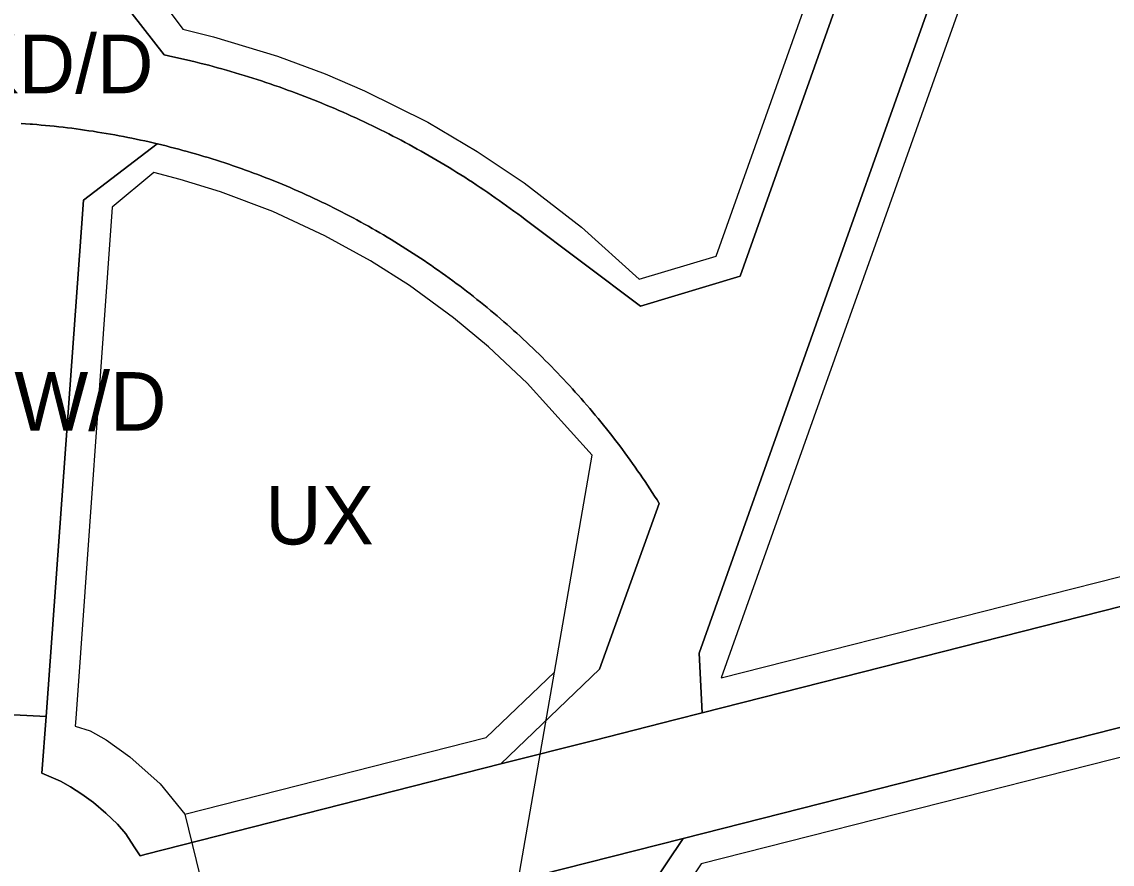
# Model space of a CAD drawing. Extents: x -297746 to -295403, y 27112 to 28877.
# Drawn here: x -297020 to -296833.6, y 27745.5 to 27889.5 of the extents above; entities that cross this region are included whole.
import ezdxf

# ---------------------------------------------------------------- set-up
doc = ezdxf.new("R2010")
doc.units = 0
for name, color, linetype in [('linie_rozgraniczajace', 7, 'Continuous'), ('linie_zabudowy_nieprzekraczalne', 7, 'Continuous'), ('linie_zabudowy_obowiazujace', 7, 'Continuous'), ('oznaczenia_przeznaczen', 7, 'Continuous')]:
    doc.layers.add(name, color=color, linetype=linetype)

msp = doc.modelspace()

# ---------------------------------------------------------------- linework, layer by layer
at = {"layer": 'linie_rozgraniczajace'}
for points in [[(-296820.49, 28048.576), (-296840.945, 27963.7), (-296846.998, 27942.631), (-296904.241, 27781.587), (-296903.708, 27771.365), (-296908.226, 27770.217), (-296922.224, 27766.659), (-296938.097, 27762.625)], [(-296746.59, 27811.296), (-296903.708, 27771.365), (-296904.241, 27781.587), (-296846.998, 27942.631), (-296840.945, 27963.7), (-296820.49, 28048.576)], [(-296943.628, 27862.473), (-296942.968, 27862.045), (-296942.311, 27861.614), (-296941.656, 27861.18), (-296941.003, 27860.742), (-296940.353, 27860.301), (-296939.704, 27859.857), (-296939.058, 27859.409), (-296938.415, 27858.959), (-296937.773, 27858.504), (-296937.134, 27858.047), (-296936.497, 27857.586), (-296935.863, 27857.123), (-296935.231, 27856.655), (-296934.601, 27856.185), (-296933.974, 27855.712), (-296914.238, 27840.894), (-296897.223, 27846.023), (-296861.256, 27947.303)], [(-296861.256, 27947.303), (-296897.223, 27846.023), (-296914.238, 27840.894)], [(-297402.243, 27914.223), (-297177, 27809.324), (-297145.09, 27794.463), (-297054.137, 27752.105), (-297051.53, 27754.599), (-297050.097, 27755.853), (-297048.619, 27756.928), (-297047.424, 27757.747), (-297047.051, 27758.003), (-297045.618, 27758.899), (-297044.095, 27759.75), (-297042.528, 27760.422), (-297040.691, 27761.138), (-297036.451, 27762.747), (-297035.795, 27771.765), (-297015.819, 27770.719), (-297016.52, 27761.077), (-297013.371, 27759.66), (-297011.669, 27758.72), (-297009.698, 27757.466), (-297007.727, 27756.032), (-297005.622, 27754.196), (-297003.607, 27752.36), (-297002.218, 27750.658)], [(-297006.58, 27897.875), (-296995.63, 27883.832), (-296994.915, 27883.68), (-296994.147, 27883.513), (-296993.38, 27883.342), (-296992.613, 27883.168), (-296991.848, 27882.989), (-296991.084, 27882.807), (-296990.32, 27882.62), (-296989.557, 27882.43), (-296988.796, 27882.236), (-296988.035, 27882.038), (-296987.276, 27881.836), (-296986.517, 27881.63), (-296985.76, 27881.421), (-296985.003, 27881.207), (-296984.248, 27880.99), (-296983.494, 27880.769), (-296982.741, 27880.544), (-296981.989, 27880.315), (-296981.238, 27880.082), (-296980.489, 27879.846), (-296979.74, 27879.606), (-296978.993, 27879.362), (-296978.247, 27879.114), (-296977.503, 27878.862), (-296976.76, 27878.607), (-296976.018, 27878.347), (-296975.277, 27878.085), (-296974.538, 27877.818), (-296973.8, 27877.547), (-296973.063, 27877.273), (-296972.328, 27876.995), (-296971.594, 27876.713), (-296970.862, 27876.428), (-296970.131, 27876.139), (-296969.402, 27875.846), (-296968.674, 27875.549), (-296967.948, 27875.249), (-296967.223, 27874.945), (-296966.5, 27874.637), (-296965.778, 27874.326), (-296965.058, 27874.011), (-296964.34, 27873.692), (-296963.623, 27873.369), (-296962.908, 27873.043), (-296962.194, 27872.714), (-296961.483, 27872.381), (-296960.773, 27872.044), (-296960.064, 27871.703), (-296959.358, 27871.359), (-296958.653, 27871.011), (-296957.95, 27870.66), (-296957.248, 27870.305), (-296956.549, 27869.947), (-296955.851, 27869.585), (-296955.156, 27869.219), (-296954.462, 27868.85), (-296953.77, 27868.478), (-296953.079, 27868.102), (-296952.391, 27867.722), (-296951.705, 27867.339), (-296951.021, 27866.952), (-296950.338, 27866.562), (-296949.658, 27866.169), (-296948.98, 27865.772), (-296948.304, 27865.371), (-296947.629, 27864.968), (-296946.957, 27864.56), (-296946.287, 27864.149), (-296945.619, 27863.735), (-296944.953, 27863.318), (-296944.289, 27862.897), (-296943.628, 27862.473)], [(-296914.238, 27840.894), (-296933.974, 27855.712), (-296934.601, 27856.185), (-296935.231, 27856.655), (-296935.863, 27857.123), (-296936.497, 27857.586), (-296937.134, 27858.047), (-296937.773, 27858.504), (-296938.415, 27858.959), (-296939.058, 27859.409), (-296939.704, 27859.857), (-296940.353, 27860.301), (-296941.003, 27860.742), (-296941.656, 27861.18), (-296942.311, 27861.614), (-296942.968, 27862.045), (-296943.628, 27862.473), (-296944.289, 27862.897), (-296944.953, 27863.318), (-296945.619, 27863.735), (-296946.287, 27864.149), (-296946.957, 27864.56), (-296947.629, 27864.968), (-296948.304, 27865.371), (-296948.98, 27865.772), (-296949.658, 27866.169), (-296950.338, 27866.562), (-296951.021, 27866.952), (-296951.705, 27867.339), (-296952.391, 27867.722), (-296953.079, 27868.102), (-296953.77, 27868.478), (-296954.462, 27868.85), (-296955.156, 27869.219), (-296955.851, 27869.585), (-296956.549, 27869.947), (-296957.248, 27870.305), (-296957.95, 27870.66), (-296958.653, 27871.011), (-296959.358, 27871.359), (-296960.064, 27871.703), (-296960.773, 27872.044), (-296961.483, 27872.381), (-296962.194, 27872.714), (-296962.908, 27873.043), (-296963.623, 27873.369), (-296964.34, 27873.692), (-296965.058, 27874.011), (-296965.778, 27874.326), (-296966.5, 27874.637), (-296967.223, 27874.945), (-296967.948, 27875.249), (-296968.674, 27875.549), (-296969.402, 27875.846), (-296970.131, 27876.139), (-296970.862, 27876.428), (-296971.594, 27876.713), (-296972.328, 27876.995), (-296973.063, 27877.273), (-296973.8, 27877.547), (-296974.538, 27877.818), (-296975.277, 27878.085), (-296976.018, 27878.347), (-296976.76, 27878.607), (-296977.503, 27878.862), (-296978.247, 27879.114), (-296978.993, 27879.362), (-296979.74, 27879.606), (-296980.489, 27879.846), (-296981.238, 27880.082), (-296981.989, 27880.315), (-296982.741, 27880.544), (-296983.494, 27880.769), (-296984.248, 27880.99), (-296985.003, 27881.207), (-296985.76, 27881.421), (-296986.517, 27881.63), (-296987.276, 27881.836), (-296988.035, 27882.038), (-296988.796, 27882.236), (-296989.557, 27882.43), (-296990.32, 27882.62), (-296991.084, 27882.807), (-296991.848, 27882.989), (-296992.613, 27883.168), (-296993.38, 27883.342), (-296994.147, 27883.513), (-296994.915, 27883.68), (-296995.63, 27883.832), (-297006.58, 27897.875)], [(-297002.218, 27750.658), (-297000.74, 27748.463), (-296999.755, 27746.94), (-296998.73, 27747.216), (-296938.097, 27762.625), (-296922.224, 27766.659), (-296908.226, 27770.217), (-296903.708, 27771.365), (-296746.59, 27811.296), (-296706.72, 27821.429), (-296451.602, 27886.266)], [(-297020.074, 27872.092), (-297019.319, 27872.044), (-297018.565, 27871.992), (-297018.125, 27871.958), (-297017.381, 27871.898), (-297016.637, 27871.834), (-297015.894, 27871.766), (-297015.152, 27871.694), (-297014.409, 27871.618), (-297013.667, 27871.538), (-297012.926, 27871.454), (-297012.185, 27871.367), (-297011.444, 27871.275), (-297010.704, 27871.179), (-297009.965, 27871.079), (-297009.226, 27870.975), (-297008.488, 27870.868), (-297007.75, 27870.756), (-297007.013, 27870.64), (-297006.276, 27870.521), (-297005.54, 27870.397), (-297004.805, 27870.27), (-297004.071, 27870.138), (-297003.337, 27870.003), (-297002.604, 27869.864), (-297001.871, 27869.721), (-297001.14, 27869.574), (-297000.409, 27869.423), (-296999.679, 27869.268), (-296998.95, 27869.109), (-296998.222, 27868.946), (-296997.495, 27868.779), (-296996.845, 27868.627), (-297009.401, 27859.009), (-297015.819, 27770.719), (-297035.795, 27771.765)], [(-296963.365, 27855.961), (-296964.024, 27856.311), (-296964.685, 27856.657), (-296965.347, 27857), (-296966.012, 27857.339), (-296966.679, 27857.675), (-296967.347, 27858.007), (-296968.017, 27858.335), (-296968.689, 27858.66), (-296969.362, 27858.981), (-296970.037, 27859.299), (-296970.714, 27859.613), (-296971.393, 27859.923), (-296972.073, 27860.23), (-296972.755, 27860.533), (-296973.438, 27860.832), (-296974.123, 27861.128), (-296974.81, 27861.42), (-296975.498, 27861.709), (-296976.188, 27861.993), (-296976.879, 27862.274), (-296977.572, 27862.552), (-296978.266, 27862.825), (-296978.962, 27863.095), (-296979.659, 27863.361), (-296980.358, 27863.623), (-296981.057, 27863.882), (-296981.759, 27864.137), (-296982.461, 27864.388), (-296983.165, 27864.635), (-296983.871, 27864.879), (-296984.577, 27865.118), (-296985.285, 27865.354), (-296985.994, 27865.587), (-296986.705, 27865.815), (-296987.416, 27866.039), (-296988.129, 27866.26), (-296988.843, 27866.477), (-296989.558, 27866.69), (-296990.274, 27866.899), (-296990.992, 27867.105), (-296991.71, 27867.306), (-296992.43, 27867.504), (-296993.15, 27867.698), (-296993.872, 27867.888), (-296994.595, 27868.074), (-296995.318, 27868.256), (-296996.043, 27868.434), (-296996.768, 27868.609), (-296996.845, 27868.627), (-296997.495, 27868.779), (-296998.222, 27868.946), (-296998.95, 27869.109), (-296999.679, 27869.268), (-297000.409, 27869.423), (-297001.14, 27869.574), (-297001.871, 27869.721), (-297002.604, 27869.864), (-297003.337, 27870.003), (-297004.071, 27870.138), (-297004.805, 27870.27), (-297005.54, 27870.397), (-297006.276, 27870.521), (-297007.013, 27870.64), (-297007.75, 27870.756), (-297008.488, 27870.868), (-297009.226, 27870.975), (-297009.965, 27871.079), (-297010.704, 27871.179), (-297011.444, 27871.275), (-297012.185, 27871.367), (-297012.926, 27871.454), (-297013.667, 27871.538), (-297014.409, 27871.618), (-297015.152, 27871.694), (-297015.894, 27871.766), (-297016.637, 27871.834), (-297017.381, 27871.898), (-297018.125, 27871.958), (-297018.565, 27871.992), (-297019.319, 27872.044), (-297020.074, 27872.092)], [(-296434.505, 27869.975), (-296706.45, 27800.862), (-296746.32, 27790.729), (-296906.963, 27749.902), (-296939.511, 27741.63), (-296994.696, 27727.605), (-296995.426, 27722.859), (-296995.977, 27720.526), (-296996.722, 27717.999), (-296996.986, 27717.325), (-296988.793, 27710.975), (-297001.433, 27695.468), (-297009.248, 27701.525), (-297010.984, 27700.354), (-297012.53, 27699.459), (-297013.954, 27698.747), (-297015.744, 27697.933), (-297017.209, 27697.364), (-297018.714, 27696.855), (-297020.158, 27696.448), (-297021.212, 27696.201), (-297026.982, 27695.447)], [(-296999.755, 27746.94), (-297000.74, 27748.463), (-297002.218, 27750.658), (-297003.607, 27752.36), (-297005.622, 27754.196), (-297007.727, 27756.032), (-297009.698, 27757.466), (-297011.669, 27758.72), (-297013.371, 27759.66), (-297016.52, 27761.077), (-297015.819, 27770.719), (-297009.401, 27859.009), (-296996.845, 27868.627), (-296996.768, 27868.609), (-296996.043, 27868.434), (-296995.318, 27868.256), (-296994.595, 27868.074), (-296993.872, 27867.888), (-296993.15, 27867.698), (-296992.43, 27867.504), (-296991.71, 27867.306), (-296990.992, 27867.105), (-296990.274, 27866.899), (-296989.558, 27866.69), (-296988.843, 27866.477), (-296988.129, 27866.26), (-296987.416, 27866.039), (-296986.705, 27865.815), (-296985.994, 27865.587), (-296985.285, 27865.354), (-296984.577, 27865.118), (-296983.871, 27864.879), (-296983.165, 27864.635), (-296982.461, 27864.388), (-296981.759, 27864.137), (-296981.057, 27863.882), (-296980.358, 27863.623), (-296979.659, 27863.361), (-296978.962, 27863.095), (-296978.266, 27862.825), (-296977.572, 27862.552), (-296976.879, 27862.274), (-296976.188, 27861.993), (-296975.498, 27861.709), (-296974.81, 27861.42), (-296974.123, 27861.128), (-296973.438, 27860.832), (-296972.755, 27860.533), (-296972.073, 27860.23), (-296971.393, 27859.923), (-296970.714, 27859.613), (-296970.037, 27859.299), (-296969.362, 27858.981), (-296968.689, 27858.66), (-296968.017, 27858.335), (-296967.347, 27858.007), (-296966.679, 27857.675), (-296966.012, 27857.339), (-296965.347, 27857), (-296964.685, 27856.657), (-296964.024, 27856.311), (-296963.365, 27855.961), (-296962.707, 27855.608), (-296962.052, 27855.251), (-296961.399, 27854.891), (-296960.747, 27854.527), (-296960.098, 27854.16), (-296959.45, 27853.789), (-296958.805, 27853.415), (-296958.161, 27853.037), (-296957.52, 27852.656), (-296956.88, 27852.271), (-296956.243, 27851.883), (-296955.608, 27851.492), (-296954.975, 27851.097), (-296954.343, 27850.698), (-296953.715, 27850.297), (-296953.088, 27849.892), (-296952.463, 27849.484), (-296951.841, 27849.072), (-296951.221, 27848.657), (-296950.603, 27848.239), (-296949.987, 27847.817), (-296949.374, 27847.392), (-296948.763, 27846.964), (-296948.154, 27846.532), (-296947.548, 27846.098), (-296946.944, 27845.66), (-296946.342, 27845.218), (-296945.742, 27844.774), (-296945.145, 27844.326), (-296944.551, 27843.875), (-296943.959, 27843.421), (-296943.369, 27842.964), (-296942.782, 27842.504), (-296942.197, 27842.04), (-296941.615, 27841.574), (-296941.035, 27841.104), (-296940.458, 27840.631), (-296939.883, 27840.155)], [(-296938.097, 27762.625), (-296921.254, 27778.809), (-296911.029, 27807.148), (-296911.427, 27807.779), (-296911.829, 27808.408), (-296912.234, 27809.034), (-296912.642, 27809.659), (-296913.054, 27810.281), (-296913.469, 27810.902), (-296913.887, 27811.519), (-296914.308, 27812.135), (-296914.733, 27812.749), (-296915.161, 27813.36), (-296915.593, 27813.968), (-296916.028, 27814.575), (-296916.465, 27815.179), (-296916.907, 27815.781), (-296917.351, 27816.38), (-296917.799, 27816.977), (-296918.249, 27817.572), (-296918.703, 27818.164), (-296919.16, 27818.754), (-296919.621, 27819.341), (-296920.084, 27819.926), (-296920.551, 27820.508), (-296921.02, 27821.088), (-296921.493, 27821.665), (-296921.969, 27822.24), (-296922.448, 27822.812), (-296922.93, 27823.382), (-296923.415, 27823.949), (-296923.903, 27824.513), (-296924.394, 27825.075), (-296924.888, 27825.634), (-296925.385, 27826.191), (-296925.885, 27826.745), (-296926.388, 27827.296), (-296926.894, 27827.844), (-296927.403, 27828.39), (-296927.915, 27828.933), (-296928.43, 27829.473), (-296928.948, 27830.011), (-296929.468, 27830.545), (-296929.991, 27831.077), (-296930.518, 27831.606), (-296931.047, 27832.132), (-296931.578, 27832.656), (-296932.113, 27833.176), (-296932.65, 27833.694), (-296933.191, 27834.209), (-296933.734, 27834.721), (-296934.279, 27835.23), (-296934.828, 27835.736), (-296935.379, 27836.239), (-296935.932, 27836.739), (-296936.489, 27837.236), (-296937.048, 27837.73), (-296937.61, 27838.221), (-296938.174, 27838.709), (-296938.741, 27839.194), (-296939.311, 27839.676), (-296939.883, 27840.155), (-296940.458, 27840.631), (-296941.035, 27841.104), (-296941.615, 27841.574), (-296942.197, 27842.04), (-296942.782, 27842.504), (-296943.369, 27842.964), (-296943.959, 27843.421), (-296944.551, 27843.875), (-296945.145, 27844.326), (-296945.742, 27844.774), (-296946.342, 27845.218), (-296946.944, 27845.66), (-296947.548, 27846.098), (-296948.154, 27846.532), (-296948.763, 27846.964), (-296949.374, 27847.392), (-296949.987, 27847.817), (-296950.603, 27848.239), (-296951.221, 27848.657), (-296951.841, 27849.072), (-296952.463, 27849.484), (-296953.088, 27849.892), (-296953.715, 27850.297), (-296954.343, 27850.698), (-296954.975, 27851.097), (-296955.608, 27851.492), (-296956.243, 27851.883), (-296956.88, 27852.271), (-296957.52, 27852.656), (-296958.161, 27853.037), (-296958.805, 27853.415), (-296959.45, 27853.789), (-296960.098, 27854.16), (-296960.747, 27854.527), (-296961.399, 27854.891), (-296962.052, 27855.251), (-296962.707, 27855.608), (-296963.365, 27855.961)], [(-296939.883, 27840.155), (-296939.311, 27839.676), (-296938.741, 27839.194), (-296938.174, 27838.709), (-296937.61, 27838.221), (-296937.048, 27837.73), (-296936.489, 27837.236), (-296935.932, 27836.739), (-296935.379, 27836.239), (-296934.828, 27835.736), (-296934.279, 27835.23), (-296933.734, 27834.721), (-296933.191, 27834.209), (-296932.65, 27833.694), (-296932.113, 27833.176), (-296931.578, 27832.656), (-296931.047, 27832.132), (-296930.518, 27831.606), (-296929.991, 27831.077), (-296929.468, 27830.545), (-296928.948, 27830.011), (-296928.43, 27829.473), (-296927.915, 27828.933), (-296927.403, 27828.39), (-296926.894, 27827.844), (-296926.388, 27827.296), (-296925.885, 27826.745), (-296925.385, 27826.191), (-296924.888, 27825.634), (-296924.394, 27825.075), (-296923.903, 27824.513), (-296923.415, 27823.949), (-296922.93, 27823.382), (-296922.448, 27822.812), (-296921.969, 27822.24), (-296921.493, 27821.665), (-296921.02, 27821.088), (-296920.551, 27820.508), (-296920.084, 27819.926), (-296919.621, 27819.341), (-296919.16, 27818.754), (-296918.703, 27818.164), (-296918.249, 27817.572), (-296917.799, 27816.977), (-296917.351, 27816.38), (-296916.907, 27815.781), (-296916.465, 27815.179), (-296916.028, 27814.575), (-296915.593, 27813.968), (-296915.161, 27813.36), (-296914.733, 27812.749), (-296914.308, 27812.135), (-296913.887, 27811.519), (-296913.469, 27810.902), (-296913.054, 27810.281), (-296912.642, 27809.659), (-296912.234, 27809.034), (-296911.829, 27808.408), (-296911.427, 27807.779), (-296911.029, 27807.148), (-296921.254, 27778.809), (-296938.097, 27762.625), (-296998.73, 27747.216), (-296999.755, 27746.94)], [(-296939.511, 27741.63), (-296906.963, 27749.902), (-296915.532, 27737.059)]]:
    msp.add_lwpolyline(points, dxfattribs=at)
msp.add_lwpolyline([(-296746.434, 27523.132), (-296917.139, 27655.438), (-296926.254, 27679.375), (-296915.532, 27737.059), (-296906.963, 27749.902), (-296746.32, 27790.729), (-296736.217, 27782.978), (-296732.893, 27529.874)], close=True, dxfattribs=at)
at = {"layer": 'linie_zabudowy_nieprzekraczalne'}
for points in [[(-296851.976, 27789.673), (-296824.597, 27796.631), (-296797.958, 27803.401), (-296749.499, 27815.717), (-296741.777, 27825.783), (-296742.434, 27875.778), (-296742.755, 27900.235), (-296743.74, 27975.234), (-296744.353, 28021.948), (-296745.685, 28072.411), (-296758.138, 28067.897), (-296770.384, 28063.942), (-296781.847, 28060.666), (-296793.481, 28057.73), (-296802.375, 28055.778), (-296811.307, 28054.009), (-296814.968, 28050.135), (-296833.03, 27975.191), (-296836.107, 27962.425), (-296842.232, 27941.104), (-296873.517, 27853.087), (-296883.689, 27824.469)], [(-296889.201, 27883.549), (-296866.059, 27948.685), (-296860.299, 27968.745), (-296841.958, 28044.848), (-296845.929, 28049.381), (-296854.699, 28048.687), (-296877.816, 28047.783), (-296905.513, 28046.928), (-296918.975, 28046.396), (-296928.537, 28045.877), (-296939.143, 28045.163), (-296951.52, 28044.146), (-296983.681, 28040.516), (-296991.91, 28031.961)], [(-296998.373, 27942.607), (-297001.702, 27900.64), (-296992.428, 27888.215), (-296987.207, 27886.934), (-296976.284, 27883.612), (-296968.152, 27880.588), (-296961.386, 27877.691), (-296950.599, 27872.302), (-296942.132, 27867.334), (-296934.129, 27861.957), (-296924.334, 27854.385), (-296914.487, 27845.474), (-296914.487, 27845.474), (-296901.324, 27849.422), (-296889.201, 27883.549)], [(-296873.104, 27627.639), (-296781.896, 27556.948), (-296755.716, 27536.657), (-296745.85, 27529.009), (-296737.931, 27532.952), (-296738.087, 27544.856), (-296738.528, 27578.409), (-296740.575, 27734.304), (-296741.182, 27780.49), (-296747.436, 27785.287), (-296791.663, 27774.047), (-296845.078, 27760.472)]]:
    msp.add_lwpolyline(points, dxfattribs=at)
at = {"layer": 'linie_zabudowy_obowiazujace'}
for points in [[(-296997.392, 27863.714), (-297004.506, 27857.817), (-297010.759, 27770.39), (-297010.854, 27769.068), (-297008.312, 27768.275), (-297005.545, 27766.759), (-297001.484, 27763.861), (-296996.322, 27759.256), (-296992.087, 27754.064), (-296940.606, 27767.148), (-296928.952, 27778.345), (-296922.524, 27815.416), (-296933.639, 27827.696), (-296940.225, 27833.915), (-296946.21, 27838.894), (-296953.74, 27844.387), (-296960.386, 27848.612), (-296968.17, 27852.902), (-296977.065, 27857.027), (-296986.015, 27860.415), (-296992.927, 27862.549), (-296997.392, 27863.714)], [(-296883.689, 27824.469), (-296900.435, 27777.357), (-296851.976, 27789.673)], [(-296928.952, 27778.345), (-296922.524, 27815.416)], [(-296937.232, 27730.596), (-296928.952, 27778.345)], [(-296845.078, 27760.472), (-296855.407, 27757.847), (-296903.867, 27745.531), (-296910.801, 27735.139), (-296920.886, 27680.878), (-296911.711, 27657.403), (-296879.704, 27632.755), (-296873.104, 27627.639)], [(-296992.087, 27754.064), (-296984.99, 27724.914)]]:
    msp.add_lwpolyline(points, dxfattribs=at)

# ---------------------------------------------------------------- texts
at = {"layer": 'oznaczenia_przeznaczen'}
for s, p in [('KD/D', (-297029.417, 27877.268)), ('KDW/D', (-297039.811, 27819.599)), ('UX', (-296978.387, 27800.143))]:
    msp.add_text(s, height=10, dxfattribs=at).set_placement(p)

doc.saveas('drawing.dxf')
